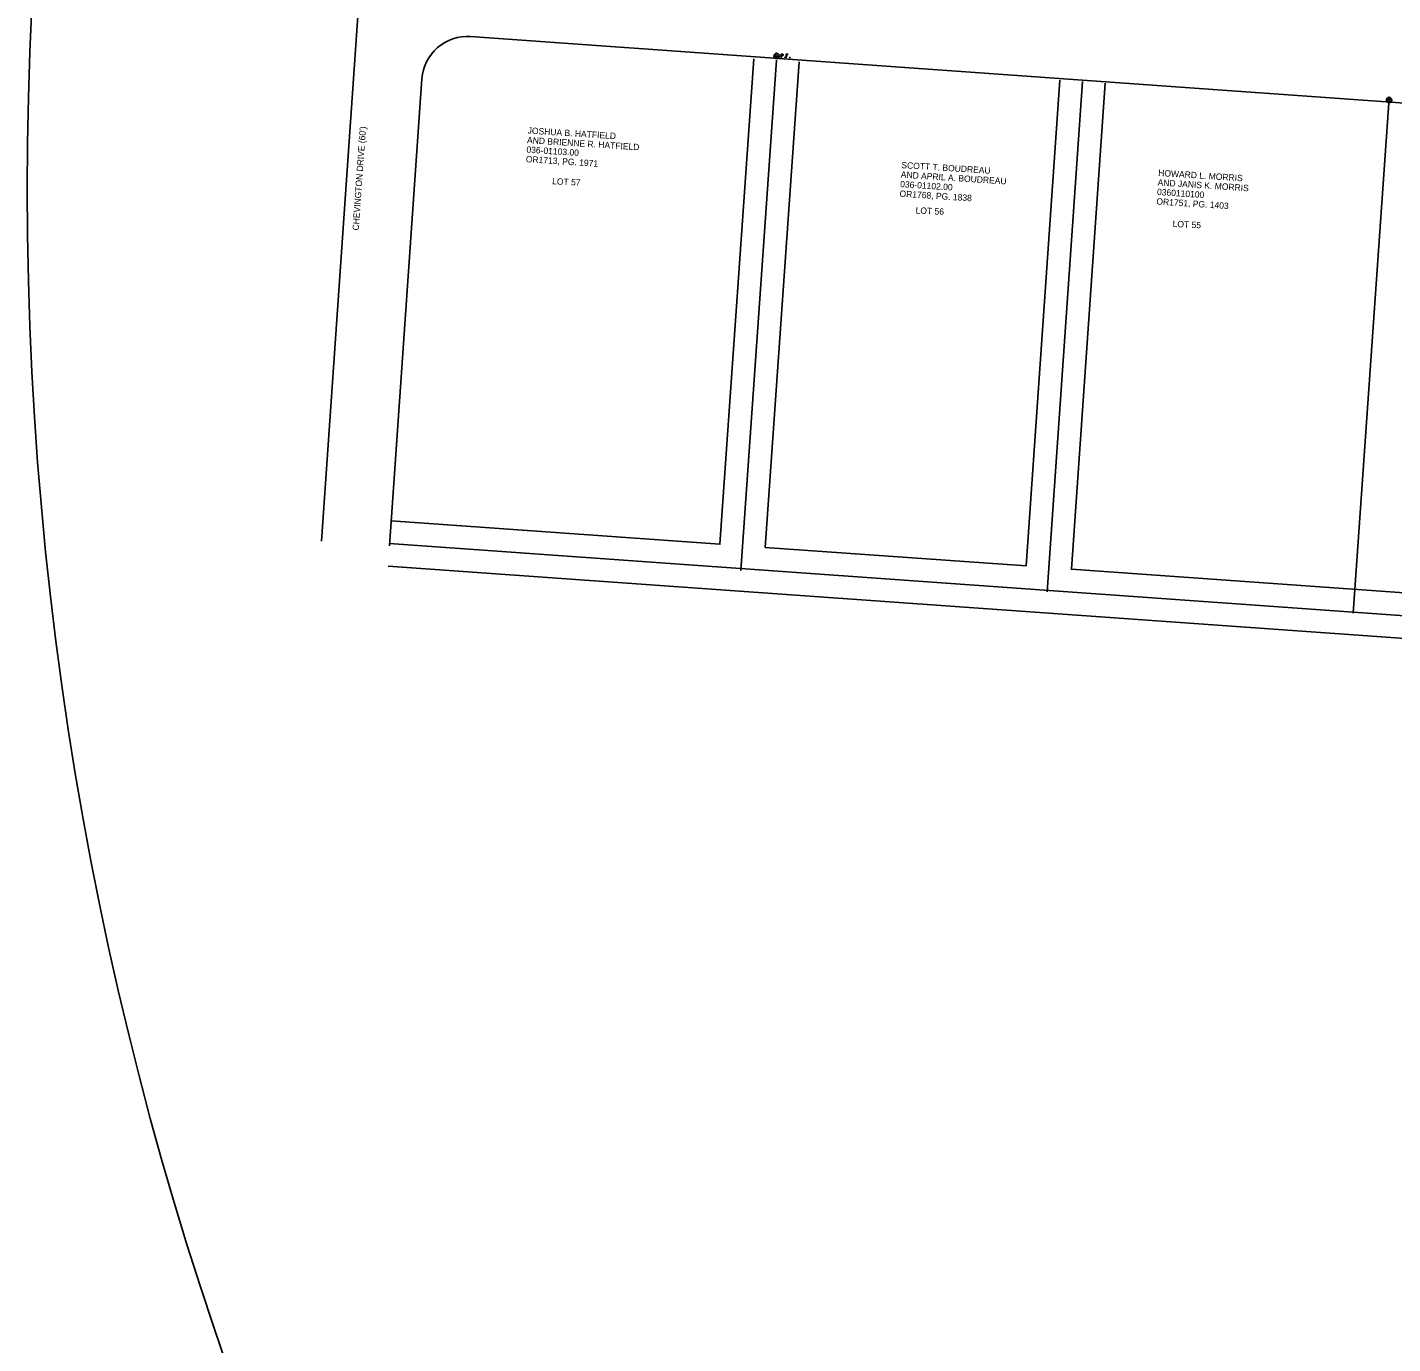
# Model space of a CAD drawing. Extents: x 1898254 to 1901377, y 701554 to 704886.
# Drawn here: x 1898254 to 1898855, y 702722 to 703301 of the extents above; entities that cross this region are included whole.
import ezdxf

# ---------------------------------------------------------------- set-up
doc = ezdxf.new("R2010")
doc.units = 0
for name, color, linetype in [('DV_X_Property_Line', 7, 'Continuous'), ('DV_X_Text', 7, 'Continuous'), ('RW_X_CL', 7, 'Continuous'), ('RW_X_Esmt_General', 7, 'Continuous'), ('RW_X_Esmt_U', 7, 'Continuous'), ('RW_X_Fee_RW', 7, 'Continuous'), ('RW_X_Text', 7, 'Continuous'), ('SC_Scratch2', 7, 'Continuous'), ('SC_Scratch5', 7, 'Continuous'), ('SV_X_Mon_Cells_Found', 7, 'Continuous')]:
    doc.layers.add(name, color=color, linetype=linetype)

msp = doc.modelspace()

# ---------------------------------------------------------------- linework, layer by layer
at = {"layer": 'DV_X_Property_Line'}
for p, q in [((1898568.34, 703062.05), (1898583.97, 703286.5)), ((1898703.01, 703052.67), (1898718.65, 703277.12)), ((1898837.69, 703043.29), (1898853.32, 703267.74)), ((1899469, 702998.85), (1898413.79, 703073.89))]:
    msp.add_line(p, q, dxfattribs=at)
at = {"layer": 'RW_X_CL'}
msp.add_line((1898383.79, 703074.9), (1898401.58, 703330.4), dxfattribs=at)
at = {"layer": 'RW_X_Esmt_General'}
for points in [[(1898414.48, 703083.87), (1898559.12, 703073.58), (1898574, 703287.2)], [(1898593.95, 703285.81), (1898579.07, 703072.16), (1898693.78, 703064.01), (1898708.67, 703277.82)], [(1898728.62, 703276.43), (1898713.73, 703062.59), (1898988.04, 703043.08)]]:
    msp.add_lwpolyline(points, dxfattribs=at)
at = {"layer": 'RW_X_Esmt_U'}
msp.add_lwpolyline([(1898413.09, 703063.91), (1899458.32, 702989.59), (1899455.83, 702954.62), (1899530.23, 702949.35), (1899466.62, 702051.43)], dxfattribs=at)
at = {"layer": 'RW_X_Fee_RW'}
for p, q in [((1898449.4, 703296.93), (1899763.77, 703203.46)), ((1898413.71, 703072.82), (1898428.03, 703278.37))]:
    msp.add_line(p, q, dxfattribs=at)
msp.add_arc((1898447.98, 703276.98), 20, 85.93252, 176.01585, dxfattribs=at)
at = {"layer": 'SC_Scratch2'}
msp.add_circle((1899815.76, 703229.84), 1561.35, dxfattribs=at)
at = {"layer": 'SC_Scratch5'}
for p, q in [((1898449.4, 703296.93), (1899763.77, 703203.46)), ((1898413.71, 703072.82), (1898428.03, 703278.37))]:
    msp.add_line(p, q, dxfattribs=at)
msp.add_arc((1898447.98, 703276.98), 20, 85.93252, 176.01585, dxfattribs=at)
at = {"layer": 'SV_X_Mon_Cells_Found'}
for points in [[(1898586.06, 703287.63), (1898586.06, 703289.23), (1898586.59, 703289.23), (1898586.65, 703289.21), (1898586.72, 703289.19), (1898586.76, 703289.16), (1898586.79, 703289.14), (1898586.83, 703289.07), (1898586.87, 703289.01), (1898586.89, 703288.91), (1898586.89, 703288.76), (1898586.88, 703288.71), (1898586.85, 703288.63), (1898586.81, 703288.55), (1898586.77, 703288.51), (1898586.73, 703288.48), (1898586.68, 703288.46), (1898586.59, 703288.44), (1898586.06, 703288.44)], [(1898587.7, 703287.84), (1898587.76, 703287.84), (1898587.79, 703287.81), (1898587.82, 703287.76), (1898587.82, 703287.7), (1898587.79, 703287.65), (1898587.76, 703287.63), (1898587.7, 703287.63), (1898587.67, 703287.65), (1898587.64, 703287.7), (1898587.64, 703287.76), (1898587.67, 703287.81), (1898587.7, 703287.84)], [(1898589.07, 703289.23), (1898588.31, 703289.23), (1898588.31, 703287.63)], [(1898588.31, 703288.44), (1898588.85, 703288.44)], [(1898589.85, 703287.84), (1898589.91, 703287.84), (1898589.94, 703287.81), (1898589.97, 703287.76), (1898589.97, 703287.7), (1898589.94, 703287.65), (1898589.91, 703287.63), (1898589.85, 703287.63), (1898589.82, 703287.65), (1898589.79, 703287.7), (1898589.79, 703287.76), (1898589.82, 703287.81), (1898589.85, 703287.84)]]:
    msp.add_lwpolyline(points, dxfattribs=at)
for centre, radius in [((1898584.06, 703288.43), 1.2), ((1898584.06, 703288.43), 0.495), ((1898853.48, 703269.02), 1.2), ((1898853.48, 703269.02), 0.495)]:
    msp.add_circle(centre, radius, dxfattribs=at)

# ---------------------------------------------------------------- texts
at = {"layer": 'DV_X_Text'}
for s, rotation, p in [('JOSHUA B. HATFIELD', 356.3351, (1898474.46, 703254.26)), ('036-01103.00', 356.3351, (1898473.92, 703245.87)), ('AND BRIENNE R. HATFIELD', 356.3351, (1898474.19, 703250.06)), ('OR1713, PG. 1971', 356.3351, (1898473.66, 703241.68)), ('AND APRIL A. BOUDREAU', 356.3351, (1898638.6, 703234.88)), ('SCOTT T. BOUDREAU', 356.3351, (1898638.86, 703239.07)), ('HOWARD L. MORRIS ', 356.3351, (1898751.86, 703235.63)), ('LOT 57', 357.09486, (1898485.25, 703231.95)), ('036-01102.00', 356.3351, (1898638.33, 703230.69)), ('AND JANIS K. MORRIS ', 356.3351, (1898751.59, 703231.43)), ('OR1768, PG. 1838', 356.3351, (1898638.06, 703226.5)), ('OR1751, PG. 1403', 356.3351, (1898751.06, 703223.05)), ('0360110100', 356.3351, (1898751.33, 703227.24)), ('LOT 56', 357.09486, (1898645.15, 703219.13)), ('LOT 55', 357.09486, (1898758.21, 703213.18))]:
    msp.add_text(s, height=2.8, rotation=rotation, dxfattribs=at).set_placement(p)
at = {"layer": 'RW_X_Text'}
msp.add_text("CHEVINGTON DRIVE (60')", height=2.8, rotation=85.93252, dxfattribs=at).set_placement((1898400.21, 703211.57))

doc.saveas('drawing.dxf')
